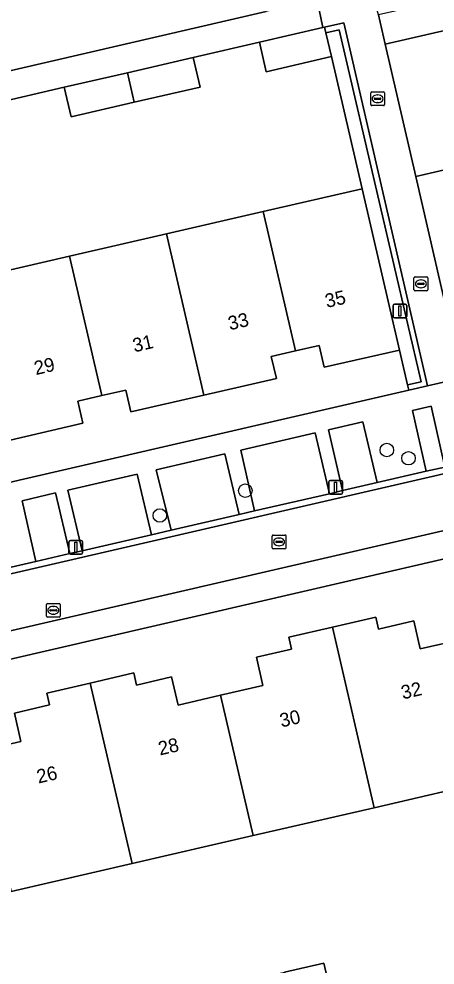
# Model space of a CAD drawing. Extents: x 156412 to 157779, y 382335 to 383768.
# Drawn here: x 156821.8 to 156851.9, y 382800.5 to 382869.1 of the extents above; entities that cross this region are included whole.
import ezdxf

# ---------------------------------------------------------------- set-up
doc = ezdxf.new("R2010")
doc.units = 0
for name, color, linetype in [('IMGEO_Berm_groen', 7, 'Continuous'), ('IMGEO_Boom', 7, 'Continuous'), ('IMGEO_Erf', 7, 'Continuous'), ('IMGEO_Groenvoorziening', 7, 'Continuous'), ('IMGEO_Kolk', 7, 'Continuous'), ('IMGEO_Lichtmast', 7, 'Continuous'), ('IMGEO_Muur', 7, 'Continuous'), ('IMGEO_Pand', 7, 'Continuous'), ('IMGEO_Pand_nummerreeks', 7, 'Continuous'), ('IMGEO_Parkeervlak_open', 7, 'Continuous'), ('IMGEO_Rijbaan_lokaal_gesloten', 7, 'Continuous'), ('IMGEO_Rijbaan_lokaal_open', 7, 'Continuous'), ('IMGEO_Rioolput', 7, 'Continuous'), ('IMGEO_Voetpad_open', 7, 'Continuous')]:
    doc.layers.add(name, color=color, linetype=linetype)

msp = doc.modelspace()

# ---------------------------------------------------------------- linework, layer by layer
at = {"layer": 'IMGEO_Berm_groen'}
msp.add_lwpolyline([(156851.654, 382841.037), (156850.308, 382840.726), (156851.309, 382836.32), (156852.648, 382836.629)], close=True, dxfattribs=at)
at = {"layer": 'IMGEO_Boom'}
for centre in [(156848.452, 382837.861), (156850.02, 382837.269), (156838.204, 382834.92), (156832.011, 382833.115)]:
    msp.add_circle(centre, 0.489, dxfattribs=at)
at = {"layer": 'IMGEO_Erf'}
for points in [[(156842.813, 382873.008), (156840.789, 382881.694), (156831.826, 382879.621), (156823.06, 382877.593), (156814.295, 382875.566), (156814.569, 382874.07), (156809.582, 382872.917), (156809.24, 382874.398), (156805.529, 382873.541), (156796.753, 382871.513), (156787.987, 382869.488), (156779.221, 382867.463), (156770.432, 382865.433), (156761.515, 382863.373), (156762.748, 382858.014), (156765.163, 382858.57), (156766.983, 382852.812), (156839.709, 382869.642), (156839.125, 382872.15), (156840.982, 382872.582)], [(156854.352, 382804.41), (156858.429, 382805.383), (156856.435, 382813.996), (156847.542, 382811.941), (156838.763, 382809.913), (156830.005, 382807.89), (156821.243, 382805.866), (156812.469, 382803.839), (156803.704, 382801.814), (156794.934, 382799.788), (156786.03, 382797.749), (156789.002, 382784.941), (156789.092, 382784.551), (156855.404, 382799.852)], [(156841.051, 382800.027), (156843.896, 382800.683), (156844.638, 382797.466), (156841.795, 382796.81), (156838.923, 382796.147), (156838.181, 382799.365)]]:
    msp.add_lwpolyline(points, close=True, dxfattribs=at)
for points in [[(156853.068, 382868.367), (156848.333, 382867.271), (156850.545, 382857.701), (156857.717, 382859.358)], [(156818.46, 382850.291), (156825.474, 382851.912), (156832.488, 382853.532), (156839.503, 382855.153), (156846.661, 382856.807), (156844.444, 382866.375), (156839.724, 382865.284), (156839.228, 382867.427), (156834.426, 382866.316), (156834.922, 382864.173), (156830.157, 382863.071), (156825.58, 382862.012), (156825.084, 382864.155), (156820.428, 382863.078)], [(156728.366, 382814.072), (156850.038, 382842.208), (156849.947, 382842.597), (156849.359, 382845.112), (156843.926, 382843.863), (156843.561, 382845.452), (156841.846, 382845.058), (156840.072, 382844.65), (156840.466, 382843.057), (156835.19, 382841.839), (156829.917, 382840.622), (156829.551, 382842.21), (156827.808, 382841.808), (156826.062, 382841.405), (156826.424, 382839.802), (156821.165, 382838.583)], [(156852.727, 382829.996), (156782.34, 382813.73)], [(156818.875, 382816.038), (156821.948, 382816.749), (156821.475, 382818.795), (156824.018, 382819.384), (156823.819, 382820.241), (156826.975, 382820.972), (156830.131, 382821.703), (156830.318, 382820.833), (156832.861, 382821.421), (156833.334, 382819.375), (156836.409, 382820.086), (156839.482, 382820.797), (156839.009, 382822.843), (156841.551, 382823.431), (156841.353, 382824.289), (156844.51, 382825.019), (156847.662, 382825.748), (156847.859, 382824.88), (156850.4, 382825.479), (156850.878, 382823.45), (156854.088, 382824.184)]]:
    msp.add_lwpolyline(points, dxfattribs=at)
at = {"layer": 'IMGEO_Groenvoorziening'}
msp.add_lwpolyline([(156849.947, 382842.597), (156850.932, 382842.818), (156845.006, 382868.331), (156844.036, 382868.109), (156844.444, 382866.375), (156846.661, 382856.807), (156849.359, 382845.112)], close=True, dxfattribs=at)
at = {"layer": 'IMGEO_Kolk'}
for p, q in [((156847.285, 382862.898), (156847.285, 382863.75)), ((156847.36, 382863.824), (156848.212, 382863.824)), ((156848.286, 382863.75), (156848.286, 382862.898)), ((156847.544, 382863.318), (156847.544, 382863.33)), ((156847.982, 382863.281), (156847.584, 382863.281)), ((156847.587, 382863.367), (156847.985, 382863.367)), ((156847.796, 382863.044), (156847.771, 382863.044)), ((156847.773, 382863.604), (156847.798, 382863.604)), ((156848.028, 382863.33), (156848.028, 382863.318)), ((156848.212, 382862.824), (156847.36, 382862.824)), ((156850.421, 382849.484), (156850.421, 382850.336)), ((156850.496, 382850.41), (156851.348, 382850.41)), ((156850.723, 382849.953), (156851.121, 382849.953)), ((156850.909, 382850.19), (156850.934, 382850.19)), ((156851.422, 382850.336), (156851.422, 382849.484)), ((156851.348, 382849.41), (156850.496, 382849.41)), ((156850.68, 382849.904), (156850.68, 382849.916)), ((156851.118, 382849.867), (156850.72, 382849.867)), ((156850.932, 382849.63), (156850.907, 382849.63)), ((156851.164, 382849.916), (156851.164, 382849.904))]:
    msp.add_line(p, q, dxfattribs=at)
for points in [[(156847.285, 382862.898), (156847.285, 382863.75)], [(156847.36, 382863.824), (156848.212, 382863.824)], [(156848.286, 382863.75), (156848.286, 382862.898)], [(156848.212, 382862.824), (156847.36, 382862.824)], [(156850.421, 382849.484), (156850.421, 382850.336)], [(156850.496, 382850.41), (156851.348, 382850.41)], [(156851.422, 382850.336), (156851.422, 382849.484)], [(156851.348, 382849.41), (156850.496, 382849.41)]]:
    msp.add_lwpolyline(points, dxfattribs=at)
for centre, radius, start, end in [((156847.362, 382863.748), 0.0765, 91.55205, 178.44795), ((156847.362, 382863.748), 0.0765, 91.55205, 178.44795), ((156848.21, 382863.748), 0.0765, 1.55205, 88.44795), ((156848.21, 382863.748), 0.0765, 1.55205, 88.44795), ((156847.584, 382863.327), 0.0403, 85.87752, 175.75265), ((156847.581, 382863.317), 0.0366, 178.93798, 274.71019), ((156847.985, 382863.324), 0.043, 264.86636, 352.45326), ((156847.989, 382863.329), 0.0386, 1.73085, 96.63898), ((156847.362, 382862.9), 0.0765, 181.55205, 268.44795), ((156847.362, 382862.9), 0.0765, 181.55205, 268.44795), ((156848.21, 382862.9), 0.0765, 271.55205, 358.44795), ((156848.21, 382862.9), 0.0765, 271.55205, 358.44795), ((156850.498, 382850.334), 0.0765, 91.55205, 178.44795), ((156850.498, 382850.334), 0.0765, 91.55205, 178.44795), ((156850.72, 382849.913), 0.0403, 85.87752, 175.75265), ((156851.125, 382849.915), 0.0386, 1.73085, 96.63898), ((156851.346, 382850.334), 0.0765, 1.55205, 88.44795), ((156851.346, 382850.334), 0.0765, 1.55205, 88.44795), ((156850.498, 382849.486), 0.0765, 181.55205, 268.44795), ((156850.498, 382849.486), 0.0765, 181.55205, 268.44795), ((156850.717, 382849.903), 0.0366, 178.93798, 274.71019), ((156851.121, 382849.91), 0.043, 264.86636, 352.45326), ((156851.346, 382849.486), 0.0765, 271.55205, 358.44795), ((156851.346, 382849.486), 0.0765, 271.55205, 358.44795)]:
    msp.add_arc(centre, radius, start, end, dxfattribs=at)
for centre, major_axis, ratio, start_param, end_param in [((156847.772, 382863.324), (-0.387, 0.002), 0.722429, 4.712389, 7.853982), ((156847.797, 382863.324), (-0.39, 0.002), 0.717154, 1.570796, 4.712389), ((156850.908, 382849.91), (-0.387, 0.002), 0.722429, 4.712389, 7.853982), ((156850.933, 382849.91), (-0.39, 0.002), 0.717154, 1.570796, 4.712389)]:
    msp.add_ellipse(centre, major_axis=major_axis, ratio=ratio, start_param=start_param, end_param=end_param, dxfattribs=at)
at = {"layer": 'IMGEO_Lichtmast'}
for p, q in [((156848.905, 382847.547), (156848.905, 382848.347)), ((156848.905, 382848.347), (156848.905, 382847.547)), ((156849.005, 382848.447), (156849.795, 382848.447)), ((156849.795, 382848.447), (156849.005, 382848.447)), ((156849.895, 382848.347), (156849.895, 382847.547)), ((156849.895, 382847.547), (156849.895, 382848.347)), ((156849.795, 382847.447), (156849.005, 382847.447)), ((156849.005, 382847.447), (156849.795, 382847.447)), ((156844.249, 382834.765), (156844.249, 382835.565)), ((156844.249, 382835.565), (156844.249, 382834.765)), ((156844.349, 382835.665), (156845.139, 382835.665)), ((156845.139, 382835.665), (156844.349, 382835.665)), ((156845.239, 382835.565), (156845.239, 382834.765)), ((156845.239, 382834.765), (156845.239, 382835.565)), ((156845.139, 382834.665), (156844.349, 382834.665)), ((156844.349, 382834.665), (156845.139, 382834.665)), ((156825.432, 382830.417), (156825.432, 382831.217)), ((156825.432, 382831.217), (156825.432, 382830.417)), ((156825.532, 382831.317), (156826.322, 382831.317)), ((156826.322, 382831.317), (156825.532, 382831.317)), ((156826.422, 382831.217), (156826.422, 382830.417)), ((156826.422, 382830.417), (156826.422, 382831.217)), ((156826.322, 382830.317), (156825.532, 382830.317)), ((156825.532, 382830.317), (156826.322, 382830.317))]:
    msp.add_line(p, q, dxfattribs=at)
for points in [[(156849.325, 382848.322), (156849.475, 382848.322), (156849.475, 382847.572), (156849.325, 382847.572), (156849.325, 382848.322)], [(156844.669, 382835.54), (156844.819, 382835.54), (156844.819, 382834.79), (156844.669, 382834.79), (156844.669, 382835.54)], [(156825.852, 382831.192), (156826.002, 382831.192), (156826.002, 382830.442), (156825.852, 382830.442), (156825.852, 382831.192)]]:
    msp.add_lwpolyline(points, dxfattribs=at)
for centre, start, end in [((156849.005, 382848.347), 90, 180), ((156849.005, 382848.347), 90, 180), ((156849.795, 382848.347), 0, 90), ((156849.795, 382848.347), 360, 90), ((156849.005, 382847.547), 180, 270), ((156849.005, 382847.547), 180, 270), ((156849.795, 382847.547), 270, 0), ((156849.795, 382847.547), 270, 0), ((156844.349, 382835.565), 90, 180), ((156844.349, 382835.565), 90, 180), ((156845.139, 382835.565), 0, 90), ((156845.139, 382835.565), 360, 90), ((156844.349, 382834.765), 180, 270), ((156844.349, 382834.765), 180, 270), ((156845.139, 382834.765), 270, 0), ((156845.139, 382834.765), 270, 0), ((156825.532, 382831.217), 90, 180), ((156825.532, 382831.217), 90, 180), ((156826.322, 382831.217), 0, 90), ((156826.322, 382831.217), 360, 90), ((156825.532, 382830.417), 180, 270), ((156825.532, 382830.417), 180, 270), ((156826.322, 382830.417), 270, 0), ((156826.322, 382830.417), 270, 0)]:
    msp.add_arc(centre, 0.1, start, end, dxfattribs=at)
at = {"layer": 'IMGEO_Muur'}
msp.add_lwpolyline([(156845.338, 382868.823), (156843.942, 382868.51), (156844.036, 382868.109), (156845.006, 382868.331), (156850.932, 382842.818), (156849.947, 382842.597), (156850.038, 382842.208), (156851.402, 382842.527)], close=True, dxfattribs=at)
msp.add_lwpolyline([(156848.333, 382867.271), (156850.545, 382857.701)], dxfattribs=at)
at = {"layer": 'IMGEO_Pand'}
for points in [[(156847.84, 382869.397), (156848.333, 382867.271), (156853.068, 382868.367), (156852.577, 382870.491)], [(156844.444, 382866.375), (156844.036, 382868.109), (156843.942, 382868.51), (156843.826, 382868.491), (156839.228, 382867.427), (156839.724, 382865.284)], [(156830.157, 382863.071), (156834.922, 382864.173), (156834.426, 382866.316), (156829.66, 382865.213)], [(156830.157, 382863.071), (156829.66, 382865.213), (156825.084, 382864.155), (156825.58, 382862.012)], [(156860.074, 382849.17), (156857.717, 382859.358), (156850.545, 382857.701), (156853.238, 382846.009), (156858.65, 382847.262), (156858.303, 382848.762)], [(156839.503, 382855.153), (156841.846, 382845.058), (156843.561, 382845.452), (156843.926, 382843.863), (156849.359, 382845.112), (156846.661, 382856.807)], [(156835.19, 382841.839), (156840.466, 382843.057), (156840.072, 382844.65), (156841.846, 382845.058), (156839.503, 382855.153), (156832.488, 382853.532)], [(156835.19, 382841.839), (156832.488, 382853.532), (156825.474, 382851.912), (156827.808, 382841.808), (156829.551, 382842.21), (156829.917, 382840.622)], [(156825.474, 382851.912), (156818.46, 382850.291), (156821.165, 382838.583), (156826.424, 382839.802), (156826.062, 382841.405), (156827.808, 382841.808)], [(156844.51, 382825.019), (156847.542, 382811.941), (156856.435, 382813.996), (156854.088, 382824.184), (156850.878, 382823.45), (156850.4, 382825.479), (156847.859, 382824.88), (156847.662, 382825.748)], [(156836.409, 382820.086), (156838.763, 382809.913), (156847.542, 382811.941), (156844.51, 382825.019), (156841.353, 382824.289), (156841.551, 382823.431), (156839.009, 382822.843), (156839.482, 382820.797)], [(156836.409, 382820.086), (156833.334, 382819.375), (156832.861, 382821.421), (156830.318, 382820.833), (156830.131, 382821.703), (156826.975, 382820.972), (156830.005, 382807.89), (156838.763, 382809.913)], [(156830.005, 382807.89), (156826.975, 382820.972), (156823.819, 382820.241), (156824.018, 382819.384), (156821.475, 382818.795), (156821.948, 382816.749), (156818.875, 382816.038), (156821.243, 382805.866)], [(156841.051, 382800.027), (156841.795, 382796.81), (156844.638, 382797.466), (156843.896, 382800.683)]]:
    msp.add_lwpolyline(points, close=True, dxfattribs=at)
at = {"layer": 'IMGEO_Parkeervlak_open'}
for points in [[(156846.725, 382839.898), (156844.218, 382839.319), (156845.248, 382834.92), (156847.754, 382835.499)], [(156843.264, 382839.098), (156837.886, 382837.855), (156838.879, 382833.449), (156844.295, 382834.7)], [(156836.719, 382837.586), (156831.751, 382836.438), (156832.824, 382832.05), (156837.763, 382833.191)], [(156830.375, 382836.12), (156825.342, 382834.957), (156826.378, 382830.562), (156831.415, 382831.725)], [(156824.461, 382834.753), (156822.031, 382834.191), (156823.035, 382829.789), (156825.494, 382830.357)]]:
    msp.add_lwpolyline(points, close=True, dxfattribs=at)
at = {"layer": 'IMGEO_Rijbaan_lokaal_gesloten'}
msp.add_lwpolyline([(156925.817, 382853.068), (156855.39, 382836.785), (156816.178, 382827.739), (156776.982, 382818.697), (156706.623, 382802.451), (156704.67, 382802.003), (156705.372, 382798.026), (156707.336, 382798.509), (156707.464, 382798.538), (156780.281, 382815.295), (156817.084, 382823.811), (156856.378, 382832.904)], dxfattribs=at)
at = {"layer": 'IMGEO_Rijbaan_lokaal_open'}
for points in [[(156704.67, 382802.003), (156706.623, 382802.451), (156776.982, 382818.697), (156816.178, 382827.739), (156855.39, 382836.785), (156925.817, 382853.068)], [(156852.648, 382836.629), (156851.309, 382836.32), (156847.754, 382835.499), (156845.248, 382834.92), (156844.295, 382834.7), (156838.879, 382833.449), (156837.763, 382833.191), (156832.824, 382832.05), (156831.415, 382831.725), (156826.378, 382830.562), (156825.494, 382830.357), (156823.035, 382829.789), (156820.711, 382829.253)]]:
    msp.add_lwpolyline(points, dxfattribs=at)
at = {"layer": 'IMGEO_Rioolput'}
for p, q in [((156840.149, 382830.778), (156840.149, 382831.63)), ((156840.224, 382831.704), (156841.076, 382831.704)), ((156840.637, 382831.484), (156840.662, 382831.484)), ((156841.15, 382831.63), (156841.15, 382830.778)), ((156840.408, 382831.198), (156840.408, 382831.21)), ((156840.846, 382831.161), (156840.448, 382831.161)), ((156840.451, 382831.247), (156840.849, 382831.247)), ((156840.66, 382830.924), (156840.635, 382830.924)), ((156840.892, 382831.21), (156840.892, 382831.198)), ((156841.076, 382830.704), (156840.224, 382830.704)), ((156823.797, 382825.822), (156823.797, 382826.674)), ((156823.872, 382826.748), (156824.724, 382826.748)), ((156824.798, 382826.674), (156824.798, 382825.822)), ((156824.056, 382826.242), (156824.056, 382826.254)), ((156824.494, 382826.205), (156824.096, 382826.205)), ((156824.099, 382826.291), (156824.497, 382826.291)), ((156824.308, 382825.968), (156824.283, 382825.968)), ((156824.285, 382826.528), (156824.31, 382826.528)), ((156824.54, 382826.254), (156824.54, 382826.242)), ((156824.724, 382825.748), (156823.872, 382825.748))]:
    msp.add_line(p, q, dxfattribs=at)
for points in [[(156840.149, 382830.778), (156840.149, 382831.63)], [(156840.224, 382831.704), (156841.076, 382831.704)], [(156841.15, 382831.63), (156841.15, 382830.778)], [(156841.076, 382830.704), (156840.224, 382830.704)], [(156823.797, 382825.822), (156823.797, 382826.674)], [(156823.872, 382826.748), (156824.724, 382826.748)], [(156824.798, 382826.674), (156824.798, 382825.822)], [(156824.724, 382825.748), (156823.872, 382825.748)]]:
    msp.add_lwpolyline(points, dxfattribs=at)
for centre, radius, start, end in [((156840.226, 382831.628), 0.0765, 91.55205, 178.44795), ((156840.226, 382831.628), 0.0765, 91.55205, 178.44795), ((156841.074, 382831.628), 0.0765, 1.55205, 88.44795), ((156841.074, 382831.628), 0.0765, 1.55205, 88.44795), ((156840.226, 382830.78), 0.0765, 181.55205, 268.44795), ((156840.226, 382830.78), 0.0765, 181.55205, 268.44795), ((156840.448, 382831.207), 0.0403, 85.87752, 175.75265), ((156840.445, 382831.197), 0.0366, 178.93798, 274.71019), ((156840.849, 382831.204), 0.043, 264.86636, 352.45326), ((156840.853, 382831.209), 0.0386, 1.73085, 96.63898), ((156841.074, 382830.78), 0.0765, 271.55205, 358.44795), ((156841.074, 382830.78), 0.0765, 271.55205, 358.44795), ((156823.874, 382826.672), 0.0765, 91.55205, 178.44795), ((156823.874, 382826.672), 0.0765, 91.55205, 178.44795), ((156824.722, 382826.672), 0.0765, 1.55205, 88.44795), ((156824.722, 382826.672), 0.0765, 1.55205, 88.44795), ((156824.096, 382826.251), 0.0403, 85.87752, 175.75265), ((156824.093, 382826.241), 0.0366, 178.93798, 274.71019), ((156824.497, 382826.248), 0.043, 264.86636, 352.45326), ((156824.501, 382826.253), 0.0386, 1.73085, 96.63898), ((156823.874, 382825.824), 0.0765, 181.55205, 268.44795), ((156823.874, 382825.824), 0.0765, 181.55205, 268.44795), ((156824.722, 382825.824), 0.0765, 271.55205, 358.44795), ((156824.722, 382825.824), 0.0765, 271.55205, 358.44795)]:
    msp.add_arc(centre, radius, start, end, dxfattribs=at)
for centre, major_axis, ratio, start_param, end_param in [((156840.636, 382831.204), (-0.387, 0.002), 0.722429, 4.712389, 7.853982), ((156840.661, 382831.204), (-0.39, 0.002), 0.717154, 1.570796, 4.712389), ((156824.284, 382826.248), (-0.387, 0.002), 0.722429, 4.712389, 7.853982), ((156824.309, 382826.248), (-0.39, 0.002), 0.717154, 1.570796, 4.712389)]:
    msp.add_ellipse(centre, major_axis=major_axis, ratio=ratio, start_param=start_param, end_param=end_param, dxfattribs=at)
at = {"layer": 'IMGEO_Voetpad_open'}
for points in [[(156847.325, 382871.335), (156844.666, 382882.629), (156841.641, 382895.717), (156840.966, 382898.64), (156838.598, 382897.917), (156844.886, 382870.834), (156843.397, 382870.5), (156843.826, 382868.491), (156843.942, 382868.51), (156845.338, 382868.823), (156851.402, 382842.527), (156853.925, 382843.103), (156853.238, 382846.009), (156850.545, 382857.701), (156848.333, 382867.271), (156847.84, 382869.397)], [(156852.727, 382829.996), (156854.08, 382830.294), (156856.714, 382830.844), (156856.91, 382830.891), (156859.126, 382831.425), (156927.114, 382847.315), (156926.664, 382849.268), (156923.197, 382848.454), (156856.378, 382832.904), (156817.084, 382823.811), (156780.281, 382815.295), (156707.464, 382798.538), (156707.908, 382796.596), (156778.432, 382812.831), (156780.962, 382813.412), (156782.34, 382813.73)]]:
    msp.add_lwpolyline(points, close=True, dxfattribs=at)
for points in [[(156778.348, 382853.343), (156783.024, 382854.424), (156787.589, 382855.48), (156792.375, 382856.588), (156797.05, 382857.669), (156801.616, 382858.726), (156806.401, 382859.833), (156811.077, 382860.914), (156815.643, 382861.971), (156820.428, 382863.078), (156825.084, 382864.155), (156829.66, 382865.213), (156834.426, 382866.316), (156839.228, 382867.427), (156843.826, 382868.491), (156843.397, 382870.5), (156839.709, 382869.642), (156766.983, 382852.812)], [(156853.925, 382843.103), (156851.402, 382842.527), (156850.038, 382842.208), (156728.366, 382814.072)], [(156820.711, 382829.253), (156823.035, 382829.789), (156822.031, 382834.191), (156824.461, 382834.753), (156825.494, 382830.357), (156826.378, 382830.562), (156825.342, 382834.957), (156830.375, 382836.12), (156831.415, 382831.725), (156832.824, 382832.05), (156831.751, 382836.438), (156836.719, 382837.586), (156837.763, 382833.191), (156838.879, 382833.449), (156837.886, 382837.855), (156843.264, 382839.098), (156844.295, 382834.7), (156845.248, 382834.92), (156844.218, 382839.319), (156846.725, 382839.898), (156847.754, 382835.499), (156851.309, 382836.32), (156850.308, 382840.726), (156851.654, 382841.037), (156852.648, 382836.629)]]:
    msp.add_lwpolyline(points, dxfattribs=at)

# ---------------------------------------------------------------- texts
at = {"layer": 'IMGEO_Pand_nummerreeks'}
for s, rotation, p in [('35', 13.00408, (156844.107, 382848.159)), ('33', 13.00408, (156837.082, 382846.537)), ('31', 13.00408, (156830.167, 382844.939)), ('29', 13.00408, (156823.032, 382843.292)), ('32', 13.00484, (156849.617, 382819.785)), ('30', 13.00484, (156840.822, 382817.753)), ('28', 13.00484, (156832.021, 382815.721)), ('26', 13.00484, (156823.218, 382813.688))]:
    msp.add_text(s, height=1, rotation=rotation, dxfattribs=at).set_placement(p)

doc.saveas('drawing.dxf')
